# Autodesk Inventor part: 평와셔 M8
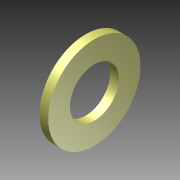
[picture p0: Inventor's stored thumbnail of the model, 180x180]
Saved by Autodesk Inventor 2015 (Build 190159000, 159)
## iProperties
Created: 2024-12
Part Number: 평와셔 M8
Material: 일반
Document SubType Name: Modeling
Designer: 102566
Density: 1 g/cm^3
Appearance: 기본값
Author: 102566
Author: jhkim
Description: 평면 와셔
Creation Date: 2024-11-28
Sending System: Autodesk Inventor 2025
Preprocessor: ST-DEVELOPER v20
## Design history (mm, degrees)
node "평와셔 M81"
body "Solid1"
node "기준1"
